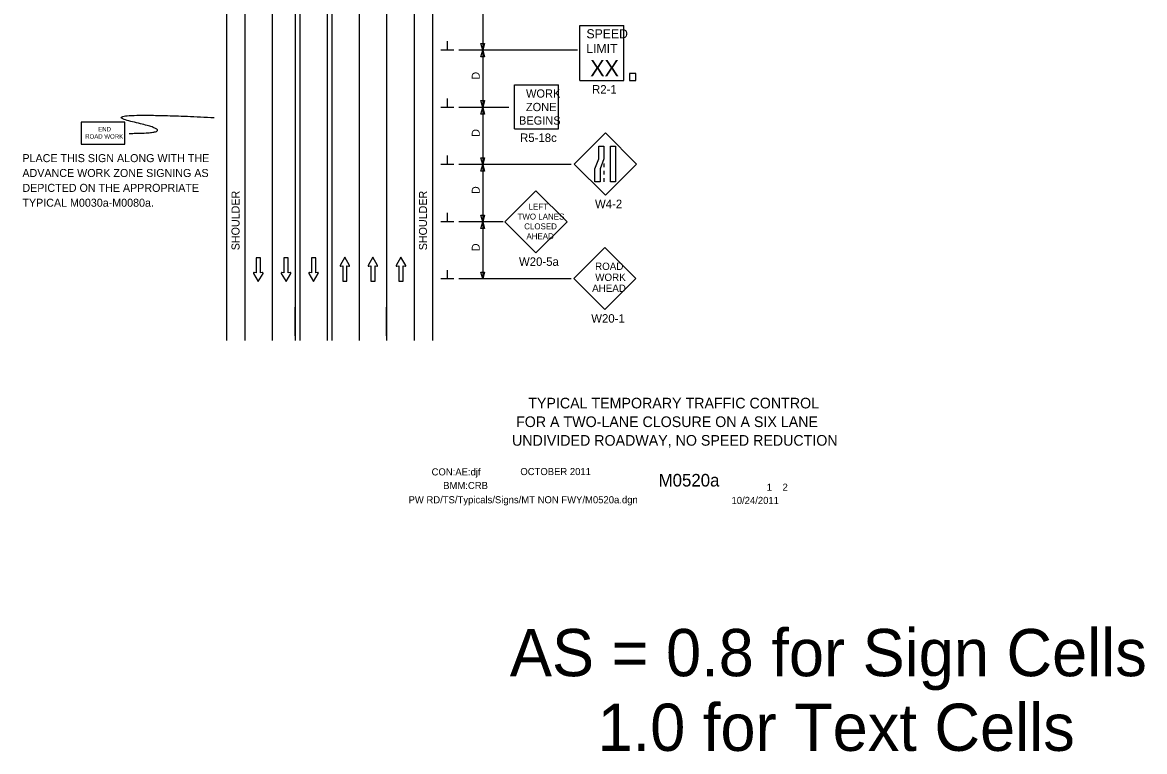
# Model space of a CAD drawing. Extents: x 16733 to 18475, y 7003 to 8205.
# Drawn here: x 16733 to 17714, y 7003 to 7640 of the extents above; entities that cross this region are included whole.
import ezdxf

# ---------------------------------------------------------------- set-up
doc = ezdxf.new("R2010")
doc.units = 0
for name, color, linetype in [('ALI_LEGAL_EX', 7, 'Continuous'), ('BORDER', 7, 'Continuous'), ('BORDER_SIGNAL_WO', 7, 'Continuous'), ('MT_SCRATCH_LEVEL_E', 7, 'Continuous'), ('PAVT_EDGE_EX', 7, 'Continuous'), ('TRAFFIC_SIGNS_PR', 7, 'Continuous'), ('TYPICAL_TEXT_DIMEN_PR', 7, 'Continuous')]:
    doc.layers.add(name, color=color, linetype=linetype)

msp = doc.modelspace()

# ---------------------------------------------------------------- linework, layer by layer
at = {"layer": 'ALI_LEGAL_EX'}
for p, q in [((16951.37, 8191.42), (16951.37, 7362.23)), ((16971.37, 8191.42), (16971.37, 7362.23)), ((16975.37, 8191.42), (16975.37, 7362.23)), ((17027.37, 8191.42), (17027.37, 7362.23)), ((17051.37, 8191.42), (17051.37, 7362.23)), ((17051.37, 8191.42), (17051.37, 7362.23))]:
    msp.add_line(p, q, dxfattribs=at)
for points in [[(16951.37, 7591.42), (16951.37, 7566.42)], [(16975.37, 7591.42), (16975.37, 7566.42)], [(17027.37, 7591.42), (17027.37, 7566.42)], [(17051.37, 7591.42), (17051.37, 7566.42)], [(16951.37, 7491.42), (16951.37, 7466.42)], [(16975.37, 7491.42), (16975.37, 7466.42)], [(17027.37, 7491.42), (17027.37, 7466.42)], [(17051.37, 7491.42), (17051.37, 7466.42)], [(16951.37, 7391.42), (16951.37, 7366.42)], [(16971.37, 7366.42), (16971.37, 7391.42)], [(16975.37, 7391.42), (16975.37, 7366.42)], [(17027.37, 7391.42), (17027.37, 7366.42)], [(17051.37, 7366.42), (17051.37, 7391.42)], [(17051.37, 7391.42), (17051.37, 7366.42)]]:
    msp.add_lwpolyline(points, dxfattribs=at)
at = {"layer": 'MT_SCRATCH_LEVEL_E'}
for p, q in [((16941.03, 7434.6), (16937.29, 7434.6)), ((16937.29, 7434.6), (16937.29, 7421.34)), ((16941.03, 7434.6), (16937.29, 7434.6)), ((16937.29, 7434.6), (16937.29, 7421.34)), ((16941.03, 7421.34), (16941.03, 7434.6)), ((16941.03, 7421.34), (16941.03, 7434.6)), ((16965.29, 7434.6), (16961.55, 7434.6)), ((16961.55, 7434.6), (16961.55, 7421.34)), ((16965.29, 7434.6), (16961.55, 7434.6)), ((16961.55, 7434.6), (16961.55, 7421.34)), ((16965.29, 7421.34), (16965.29, 7434.6)), ((16965.29, 7421.34), (16965.29, 7434.6)), ((16989.39, 7434.6), (16985.65, 7434.6)), ((16985.65, 7434.6), (16985.65, 7421.34)), ((16989.39, 7434.6), (16985.65, 7434.6)), ((16985.65, 7434.6), (16985.65, 7421.34)), ((16989.39, 7421.34), (16989.39, 7434.6)), ((16989.39, 7421.34), (16989.39, 7434.6)), ((17014.8, 7435.06), (17010.69, 7427.82)), ((17014.8, 7435.06), (17010.69, 7427.82)), ((17018.95, 7427.82), (17014.8, 7435.06)), ((17018.95, 7427.82), (17014.8, 7435.06)), ((17039.33, 7435.06), (17035.22, 7427.82)), ((17039.33, 7435.06), (17035.22, 7427.82)), ((17043.48, 7427.82), (17039.33, 7435.06)), ((17043.48, 7427.82), (17039.33, 7435.06)), ((17063.89, 7435.06), (17059.78, 7427.82)), ((17063.89, 7435.06), (17059.78, 7427.82)), ((17068.04, 7427.82), (17063.89, 7435.06)), ((17068.04, 7427.82), (17063.89, 7435.06)), ((16935.04, 7420.97), (16939.18, 7413.73)), ((16935.04, 7420.97), (16939.18, 7413.73)), ((16937.29, 7421.34), (16935.52, 7421.66)), ((16937.29, 7421.34), (16935.52, 7421.66)), ((16939.18, 7413.73), (16943.29, 7420.97)), ((16939.18, 7413.73), (16943.29, 7420.97)), ((16942.81, 7421.66), (16941.03, 7421.34)), ((16942.81, 7421.66), (16941.03, 7421.34)), ((16959.29, 7420.97), (16963.44, 7413.73)), ((16959.29, 7420.97), (16963.44, 7413.73)), ((16961.55, 7421.34), (16959.77, 7421.66)), ((16961.55, 7421.34), (16959.77, 7421.66)), ((16963.44, 7413.73), (16967.55, 7420.97)), ((16963.44, 7413.73), (16967.55, 7420.97)), ((16967.07, 7421.66), (16965.29, 7421.34)), ((16967.07, 7421.66), (16965.29, 7421.34)), ((16983.4, 7420.97), (16987.54, 7413.73)), ((16983.4, 7420.97), (16987.54, 7413.73)), ((16985.65, 7421.34), (16983.87, 7421.66)), ((16985.65, 7421.34), (16983.87, 7421.66)), ((16987.54, 7413.73), (16991.65, 7420.97)), ((16987.54, 7413.73), (16991.65, 7420.97)), ((16991.17, 7421.66), (16989.39, 7421.34)), ((16991.17, 7421.66), (16989.39, 7421.34)), ((17011.17, 7427.13), (17012.95, 7427.45)), ((17011.17, 7427.13), (17012.95, 7427.45)), ((17012.95, 7427.45), (17012.95, 7414.19)), ((17012.95, 7427.45), (17012.95, 7414.19)), ((17016.69, 7414.19), (17016.69, 7427.45)), ((17016.69, 7427.45), (17018.47, 7427.13)), ((17016.69, 7414.19), (17016.69, 7427.45)), ((17016.69, 7427.45), (17018.47, 7427.13)), ((17035.7, 7427.13), (17037.48, 7427.45)), ((17035.7, 7427.13), (17037.48, 7427.45)), ((17037.48, 7427.45), (17037.48, 7414.19)), ((17037.48, 7427.45), (17037.48, 7414.19)), ((17041.22, 7414.19), (17041.22, 7427.45)), ((17041.22, 7427.45), (17043, 7427.13)), ((17041.22, 7414.19), (17041.22, 7427.45)), ((17041.22, 7427.45), (17043, 7427.13)), ((17060.26, 7427.13), (17062.04, 7427.45)), ((17060.26, 7427.13), (17062.04, 7427.45)), ((17062.04, 7427.45), (17062.04, 7414.19)), ((17062.04, 7427.45), (17062.04, 7414.19)), ((17065.78, 7414.19), (17065.78, 7427.45)), ((17065.78, 7427.45), (17067.56, 7427.13)), ((17065.78, 7414.19), (17065.78, 7427.45)), ((17065.78, 7427.45), (17067.56, 7427.13)), ((17012.95, 7414.19), (17016.69, 7414.19)), ((17012.95, 7414.19), (17016.69, 7414.19)), ((17037.48, 7414.19), (17041.22, 7414.19)), ((17037.48, 7414.19), (17041.22, 7414.19)), ((17062.04, 7414.19), (17065.78, 7414.19)), ((17062.04, 7414.19), (17065.78, 7414.19))]:
    msp.add_line(p, q, dxfattribs=at)
for centre, start, end in [((17011.1, 7427.59), 150.42484, 279.96381), ((17011.1, 7427.59), 150.42484, 279.96381), ((17018.54, 7427.59), 260.03619, 29.77312), ((17018.54, 7427.59), 260.03619, 29.77312), ((17035.63, 7427.59), 150.42484, 279.96381), ((17035.63, 7427.59), 150.42484, 279.96381), ((17043.07, 7427.59), 260.03619, 29.77312), ((17043.07, 7427.59), 260.03619, 29.77312), ((17060.19, 7427.59), 150.42484, 279.96381), ((17060.19, 7427.59), 150.42484, 279.96381), ((17067.63, 7427.59), 260.03619, 29.77312), ((17067.63, 7427.59), 260.03619, 29.77312), ((16935.45, 7421.2), 80.03619, 209.77312), ((16935.45, 7421.2), 80.03619, 209.77312), ((16942.89, 7421.2), 330.42484, 99.96381), ((16942.89, 7421.2), 330.42484, 99.96381), ((16959.7, 7421.2), 80.03619, 209.77312), ((16959.7, 7421.2), 80.03619, 209.77312), ((16967.14, 7421.2), 330.42484, 99.96381), ((16967.14, 7421.2), 330.42484, 99.96381), ((16983.8, 7421.2), 80.03619, 209.77312), ((16983.8, 7421.2), 80.03619, 209.77312), ((16991.25, 7421.2), 330.42484, 99.96381), ((16991.25, 7421.2), 330.42484, 99.96381)]:
    msp.add_arc(centre, 0.463, start, end, dxfattribs=at)
at = {"layer": 'PAVT_EDGE_EX'}
for p, q in [((16911.37, 8191.42), (16911.37, 7362.23)), ((16927.37, 8191.42), (16927.37, 7362.23)), ((16999.37, 8191.42), (16999.37, 7362.23)), ((17003.37, 8191.42), (17003.37, 7362.23)), ((17075.37, 8191.42), (17075.37, 7362.23)), ((17091.37, 8191.42), (17091.37, 7362.23))]:
    msp.add_line(p, q, dxfattribs=at)
at = {"layer": 'TRAFFIC_SIGNS_PR'}
for p, q in [((17220.32, 7637.59), (17258.72, 7637.59)), ((17220.32, 7589.59), (17220.32, 7637.59)), ((17258.72, 7589.59), (17258.72, 7637.59)), ((17163.26, 7547.27), (17163.26, 7585.67)), ((17163.26, 7585.67), (17201.66, 7585.67)), ((17201.66, 7547.27), (17201.66, 7585.67)), ((17220.32, 7589.59), (17258.72, 7589.59)), ((17163.26, 7547.27), (17201.66, 7547.27)), ((17242.62, 7543.72), (17215.47, 7516.57)), ((17269.77, 7516.57), (17242.62, 7543.72)), ((17215.47, 7516.57), (17242.62, 7489.42)), ((17241.37, 7517.06), (17241.37, 7513.86)), ((17242.62, 7489.42), (17269.77, 7516.57)), ((17241.37, 7510.66), (17241.37, 7507.46)), ((17241.37, 7504.26), (17241.37, 7501.06)), ((17181.96, 7493.28), (17154.81, 7466.12)), ((17209.11, 7466.12), (17181.96, 7493.28)), ((17154.81, 7466.12), (17181.96, 7438.97)), ((17181.96, 7438.97), (17209.11, 7466.12)), ((17242.13, 7443.6), (17214.97, 7416.45)), ((17269.28, 7416.45), (17242.13, 7443.6)), ((17214.97, 7416.45), (17242.13, 7389.29)), ((17242.13, 7389.29), (17269.28, 7416.45))]:
    msp.add_line(p, q, dxfattribs=at)
for points in [[(17263.74, 7589.59), (17269.33, 7589.59), (17269.33, 7595.76), (17263.74, 7595.76)], [(16784.19, 7534.01), (16822.59, 7534.01), (16822.59, 7553.21), (16784.19, 7553.21)], [(17241.37, 7532.31), (17241.37, 7521.12), (17238.03, 7512.24), (17238.03, 7501.06), (17233.53, 7501.06), (17233.53, 7512.24), (17236.88, 7521.12), (17236.88, 7532.31)], [(17251.51, 7532.31), (17251.51, 7501.06), (17247.02, 7501.06), (17247.02, 7532.31)]]:
    msp.add_lwpolyline(points, close=True, dxfattribs=at)
msp.add_open_spline([(16826.19, 7543.39), (16873.42, 7543.39), (16788.4, 7562.74), (16900.7, 7557.25)], degree=2, dxfattribs=at)
at = {"layer": 'TYPICAL_TEXT_DIMEN_PR'}
for p, q in [((17135.37, 7666.14), (17135.37, 7616.14)), ((17104.49, 7616.14), (17104.49, 7623.92)), ((17110.12, 7616.14), (17098.87, 7616.14)), ((17218.26, 7616.14), (17114.37, 7616.14)), ((17135.37, 7616.14), (17133.8, 7622)), ((17133.8, 7622), (17135.37, 7622)), ((17135.37, 7616.14), (17133.8, 7622)), ((17133.8, 7622), (17135.37, 7622)), ((17133.8, 7610.28), (17135.37, 7616.14)), ((17133.8, 7610.28), (17135.37, 7616.14)), ((17135.37, 7622), (17136.94, 7622)), ((17136.94, 7622), (17135.37, 7616.14)), ((17135.37, 7622), (17136.94, 7622)), ((17136.94, 7622), (17135.37, 7616.14)), ((17135.37, 7616.14), (17135.37, 7566.14)), ((17135.37, 7616.14), (17136.94, 7610.28)), ((17135.37, 7616.14), (17136.94, 7610.28)), ((17135.37, 7610.28), (17133.8, 7610.28)), ((17135.37, 7610.28), (17133.8, 7610.28)), ((17136.94, 7610.28), (17135.37, 7610.28)), ((17136.94, 7610.28), (17135.37, 7610.28)), ((17110.12, 7566.14), (17098.87, 7566.14)), ((17104.49, 7566.14), (17104.49, 7573.92)), ((17158.14, 7566.14), (17114.37, 7566.14)), ((17135.37, 7566.14), (17133.8, 7572)), ((17133.8, 7572), (17135.37, 7572)), ((17135.37, 7566.14), (17133.8, 7572)), ((17133.8, 7572), (17135.37, 7572)), ((17133.8, 7560.28), (17135.37, 7566.14)), ((17135.37, 7572), (17136.94, 7572)), ((17136.94, 7572), (17135.37, 7566.14)), ((17135.37, 7572), (17136.94, 7572)), ((17136.94, 7572), (17135.37, 7566.14)), ((17135.37, 7566.14), (17135.37, 7516.14)), ((17135.37, 7566.14), (17136.94, 7560.28)), ((17135.37, 7560.28), (17133.8, 7560.28)), ((17136.94, 7560.28), (17135.37, 7560.28)), ((17110.12, 7516.14), (17098.87, 7516.14)), ((17104.49, 7516.14), (17104.49, 7523.92)), ((17212.66, 7516.14), (17114.37, 7516.14)), ((17135.37, 7516.14), (17133.8, 7522)), ((17133.8, 7522), (17135.37, 7522)), ((17133.8, 7510.28), (17135.37, 7516.14)), ((17135.37, 7522), (17136.94, 7522)), ((17136.94, 7522), (17135.37, 7516.14)), ((17135.37, 7516.14), (17135.37, 7466.14)), ((17135.37, 7516.14), (17136.94, 7510.28)), ((17135.37, 7510.28), (17133.8, 7510.28)), ((17136.94, 7510.28), (17135.37, 7510.28)), ((17104.49, 7466.14), (17104.49, 7473.92)), ((17135.37, 7466.14), (17133.8, 7472)), ((17133.8, 7472), (17135.37, 7472)), ((17135.37, 7466.14), (17133.8, 7472)), ((17133.8, 7472), (17135.37, 7472)), ((17135.37, 7472), (17136.94, 7472)), ((17136.94, 7472), (17135.37, 7466.14)), ((17135.37, 7472), (17136.94, 7472)), ((17136.94, 7472), (17135.37, 7466.14)), ((17110.12, 7466.14), (17098.87, 7466.14)), ((17153.37, 7466.14), (17114.37, 7466.14)), ((17133.8, 7460.28), (17135.37, 7466.14)), ((17135.37, 7460.28), (17133.8, 7460.28)), ((17135.37, 7466.14), (17135.37, 7416.14)), ((17135.37, 7466.14), (17136.94, 7460.28)), ((17136.94, 7460.28), (17135.37, 7460.28)), ((17104.49, 7416.14), (17104.49, 7423.92)), ((17135.37, 7416.14), (17133.8, 7422)), ((17133.8, 7422), (17135.37, 7422)), ((17135.37, 7422), (17136.94, 7422)), ((17136.94, 7422), (17135.37, 7416.14)), ((17110.12, 7416.14), (17098.87, 7416.14)), ((17212.66, 7416.14), (17114.37, 7416.14))]:
    msp.add_line(p, q, dxfattribs=at)

# ---------------------------------------------------------------- texts
at = {"layer": 'BORDER'}
for s, p in [('TYPICAL TEMPORARY TRAFFIC CONTROL', (17175.21, 7302.9)), ('FOR A TWO-LANE CLOSURE ON A SIX LANE', (17164.56, 7286.6)), ('UNDIVIDED ROADWAY, NO SPEED REDUCTION', (17161.04, 7270.3))]:
    msp.add_text(s, height=9.3, dxfattribs=at).set_placement(p)
at = {"layer": 'BORDER_SIGNAL_WO'}
for s, height, p in [('    OCTOBER 2011    ', 6.2, (17159.08, 7244.59)), ('CON:AE:djf', 6.2, (17090.69, 7244.31)), ('    M0520a   ', 11, (17272.86, 7234.63)), ('BMM:CRB   ', 6.2, (17100.81, 7232.42)), (' 1    2 ', 6.2, (17381.45, 7230.95)), ('PW RD/TS/Typicals/Signs/MT NON FWY/M0520a.dgn    ', 6.2, (17070.55, 7219.96)), ('10/24/2011    ', 6.2, (17352.93, 7219.38)), ('AS = 0.8 for Sign Cells', 41.2877, (17159.1, 7068.77)), ('     1.0 for Text Cells', 41.2877, (17159.1, 7003.48))]:
    msp.add_text(s, height=height, dxfattribs=at).set_placement(p)
at = {"layer": 'TRAFFIC_SIGNS_PR'}
for s, height, p in [('SPEED', 8, (17226.09, 7626.45)), ('LIMIT', 8, (17225.93, 7613.65)), ('XX', 14.031, (17229.43, 7593.35)), ('R2-1', 7.44, (17231, 7578.15)), ('WORK', 7.217, (17173.25, 7574.64)), ('ZONE', 7.217, (17173.14, 7562.82)), ('BEGINS', 7.217, (17167.06, 7551.02)), ('END', 3.831, (16799.19, 7545.14)), ('ROAD WORK', 3.831, (16787.8, 7538.76)), ('R5-18c', 7.44, (17168.07, 7535.83)), ('PLACE THIS SIGN ALONG WITH THE', 7, (16732.91, 7518.23)), ('ADVANCE WORK ZONE SIGNING AS', 7, (16732.91, 7505.23)), ('DEPICTED ON THE APPROPRIATE', 7, (16732.91, 7492.23)), ('TYPICAL M0030a-M0080a.', 7, (16732.91, 7479.23)), ('LEFT', 5.2, (17175.5, 7476.66)), ('W4-2', 7.44, (17233.58, 7477.98)), ('TWO LANES', 5.2, (17165.82, 7468.06)), ('CLOSED', 5.2, (17171.67, 7459.46)), ('AHEAD', 5.2, (17173.62, 7450.86)), ('W20-5a', 7.44, (17167.1, 7427.53)), ('ROAD', 6.4, (17233.67, 7423.98)), ('WORK', 6.4, (17233.78, 7414.38)), ('AHEAD', 6.4, (17231.09, 7404.78)), ('W20-1', 7.44, (17230.3, 7377.86))]:
    msp.add_text(s, height=height, dxfattribs=at).set_placement(p)
at = {"layer": 'TYPICAL_TEXT_DIMEN_PR'}
for s, p in [('D', (17132.81, 7590.36)), ('D', (17132.81, 7540.36)), ('D', (17132.81, 7490.36)), ('SHOULDER', (16922.74, 7441.17)), ('SHOULDER', (17086.65, 7441.17)), ('D', (17132.81, 7440.36))]:
    msp.add_text(s, height=7, rotation=90, dxfattribs=at).set_placement(p)

doc.saveas('drawing.dxf')
